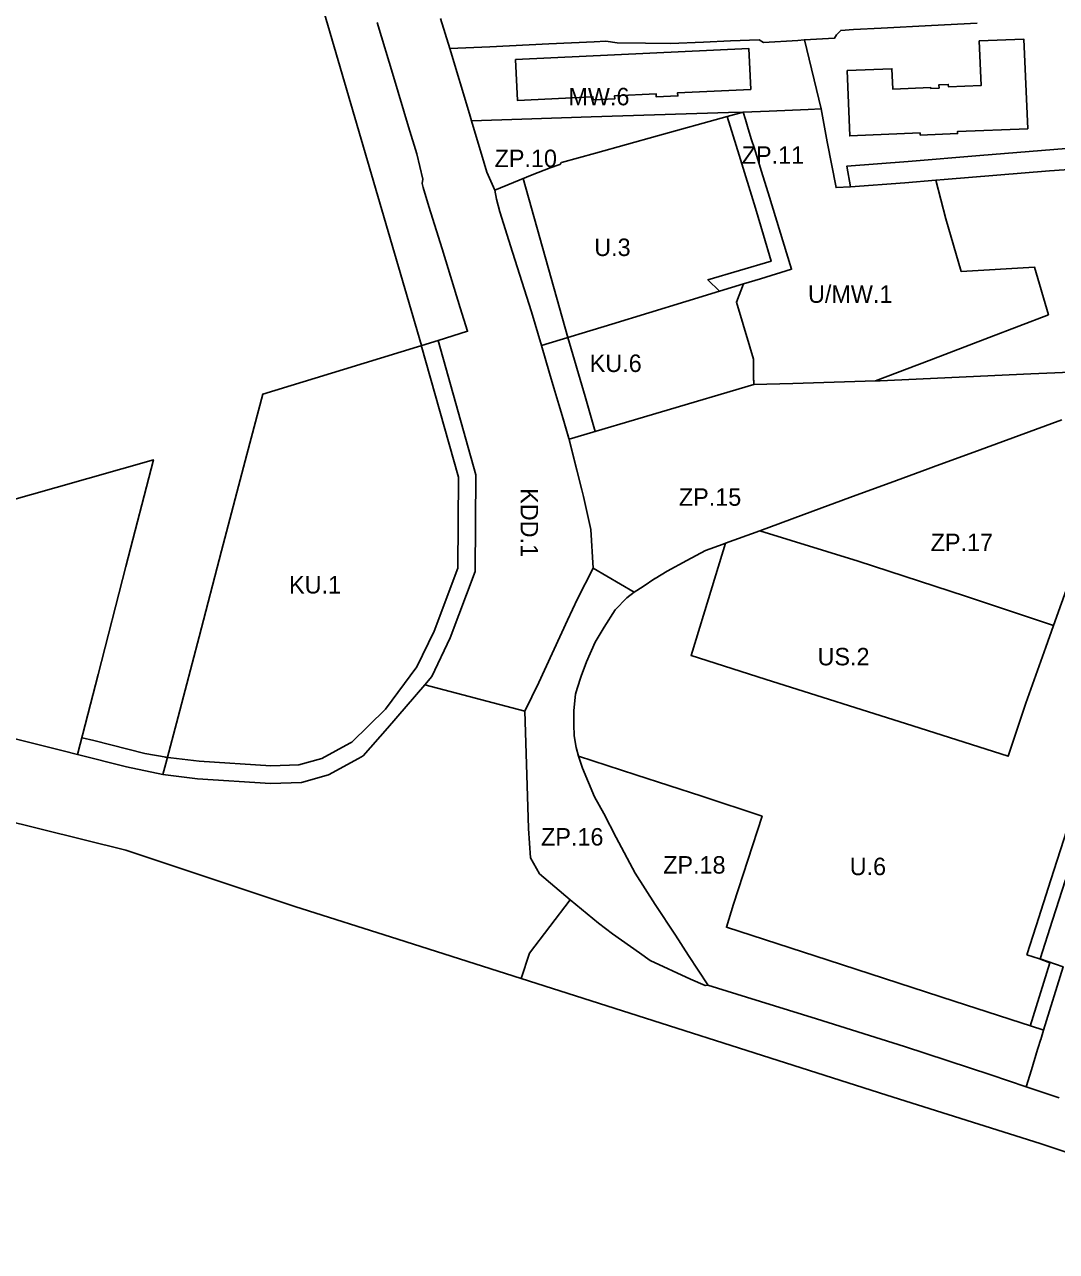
# Model space of a CAD drawing. Extents: x 7429178 to 7430831, y 5550228 to 5551611.
# Drawn here: x 7429876.2 to 7430171.5, y 5550864.2 to 5551215.2 of the extents above; entities that cross this region are included whole.
import ezdxf

# ---------------------------------------------------------------- set-up
doc = ezdxf.new("R2010")
doc.units = 0
for name, color, linetype in [('linie rozgraniczające', 7, 'Continuous'), ('nieprzekraczalne linie zabudowy', 7, 'Continuous'), ('obowiazujace linie zabudowy', 7, 'Continuous'), ('przeznaczenia terenów', 7, 'Continuous')]:
    doc.layers.add(name, color=color, linetype=linetype)

msp = doc.modelspace()

# ---------------------------------------------------------------- linework, layer by layer
at = {"layer": 'linie rozgraniczające'}
for points in [[(7429977.04, 5551215.75), (7429981.74, 5551200.32), (7429986.06, 5551185.97), (7429988.4, 5551178.21), (7429990.18, 5551170.95), (7429989.99, 5551169.68), (7429990.28, 5551168.62), (7429991.91, 5551163.18), (7429995.67, 5551151.03), (7430000.88, 5551134.16), (7430002.96, 5551127.44), (7430002.97, 5551127.43), (7429994.53, 5551124.85), (7429967.42, 5551116.51), (7429944.33, 5551109.41), (7429939.81, 5551092.17), (7429932.57, 5551064.59), (7429926.14, 5551040.05), (7429920.12, 5551017.1), (7429916.61, 5551003.74), (7429915.8, 5551000.65), (7429905.4, 5551002.83), (7429891.35, 5551006.35), (7429897.25, 5551029.27), (7429905.2, 5551060.11), (7429913.07, 5551090.69), (7429885.24, 5551082.78), (7429843.5, 5551070.94)], [(7429995.24, 5551216.96), (7429997.85, 5551208.32), (7430003.5, 5551189.65), (7430004.09, 5551187.66), (7430007.74, 5551175.52), (7430008.49, 5551173.01), (7430010.8, 5551167.85), (7430011.24, 5551165.28), (7430012.16, 5551161.61), (7430015.8, 5551150.1), (7430021.21, 5551133), (7430024.08, 5551123.34), (7430026.41, 5551115.47), (7430027.67, 5551111.24), (7430029.07, 5551106.52), (7430030.02, 5551103.31), (7430031.83, 5551097.19), (7430034.23, 5551087.73), (7430035.66, 5551082.05), (7430036.13, 5551080.22), (7430038.22, 5551070.72), (7430038.91, 5551059.68), (7430034.39, 5551050.87), (7430031.58, 5551044.81), (7430023.32, 5551026.92), (7430019.33, 5551018.76), (7429990.74, 5551026.27), (7429992.71, 5551028.7), (7429997.99, 5551039.71), (7430005.13, 5551058.76), (7430005.31, 5551086.38), (7429994.53, 5551124.85), (7430002.97, 5551127.43), (7430002.96, 5551127.44), (7430000.88, 5551134.16), (7429995.67, 5551151.03), (7429991.91, 5551163.18), (7429990.28, 5551168.62), (7429989.99, 5551169.68), (7429990.18, 5551170.95), (7429988.4, 5551178.21), (7429986.06, 5551185.97), (7429981.74, 5551200.32), (7429977.04, 5551215.75)], [(7430148.74, 5551215.55), (7430135.73, 5551214.89), (7430121.35, 5551214.15), (7430113.35, 5551213.78), (7430109.76, 5551213.53), (7430108.48, 5551212.25), (7430107.97, 5551211.33), (7430099.4, 5551210.8), (7430099.4, 5551210.8), (7430099.29, 5551210.79), (7430097.5, 5551210.68), (7430087.62, 5551210.09), (7430086.37, 5551210.87), (7430078.2, 5551210.53), (7430070.44, 5551210.12), (7430061.03, 5551209.8), (7430053.91, 5551209.87), (7430045.78, 5551209.94), (7430042.52, 5551210.44), (7430039.2, 5551210.29), (7430026.17, 5551209.67), (7430009.28, 5551208.86), (7429997.85, 5551208.32), (7429995.24, 5551216.96)], [(7430177.75, 5551180), (7430149.51, 5551177.75), (7430129.07, 5551175.98), (7430111.5, 5551174.69), (7430112.5, 5551168.78), (7430108.38, 5551168.53), (7430105.89, 5551181.65), (7430104.1, 5551191.07), (7430099.4, 5551210.8), (7430107.97, 5551211.33), (7430108.48, 5551212.25), (7430109.76, 5551213.53), (7430113.35, 5551213.78), (7430121.35, 5551214.15), (7430135.73, 5551214.89), (7430148.74, 5551215.55)], [(7430190.47, 5551174.81), (7430169.48, 5551173.32), (7430139.3, 5551170.86), (7430136.95, 5551170.65), (7430128.1, 5551169.87), (7430112.5, 5551168.78), (7430111.5, 5551174.69), (7430129.07, 5551175.98), (7430149.51, 5551177.75), (7430177.75, 5551180)], [(7430196.03, 5551116.65), (7430164.1, 5551115.22), (7430120.97, 5551113.28), (7430119.64, 5551113.24), (7430135.04, 5551119.12), (7430152.21, 5551125.68), (7430169.17, 5551132.16), (7430165.19, 5551145.77), (7430144.24, 5551144.57), (7430139.84, 5551159.6), (7430136.95, 5551170.65), (7430139.3, 5551170.86), (7430169.48, 5551173.32), (7430190.47, 5551174.81)], [(7430172.97, 5551102.13), (7430146.79, 5551092.52), (7430137.07, 5551088.95), (7430134.79, 5551088.11), (7430125.69, 5551084.77), (7430112.35, 5551079.87), (7430101.76, 5551075.98), (7430086.54, 5551070.39), (7430076.8, 5551066.81), (7430076.06, 5551066.54), (7430071.05, 5551064.7), (7430065.71, 5551061.82), (7430060.07, 5551058.78), (7430056.63, 5551056.73), (7430056.57, 5551056.69), (7430053.22, 5551054.44), (7430050.67, 5551052.81), (7430038.91, 5551059.68), (7430038.22, 5551070.72), (7430036.13, 5551080.22), (7430035.66, 5551082.05), (7430034.23, 5551087.73), (7430032, 5551096.54), (7430084.84, 5551112.21), (7430096.05, 5551112.54), (7430119.64, 5551113.24), (7430120.97, 5551113.28), (7430164.1, 5551115.22), (7430196.03, 5551116.65)], [(7430177.48, 5551062.44), (7430170.65, 5551043.22), (7430145.39, 5551051.68), (7430114.76, 5551061.67), (7430086.54, 5551070.39), (7430101.76, 5551075.98), (7430112.35, 5551079.87), (7430125.69, 5551084.77), (7430134.79, 5551088.11), (7430137.07, 5551088.95), (7430146.79, 5551092.52), (7430172.97, 5551102.13)], [(7429843.5, 5551070.94), (7429885.24, 5551082.78), (7429913.07, 5551090.69), (7429905.2, 5551060.11), (7429897.25, 5551029.27), (7429891.35, 5551006.35), (7429887.28, 5551007.37), (7429848.25, 5551017.16)], [(7430173.35, 5550945.62), (7430167.77, 5550927.5), (7430167.6, 5550927.55), (7430142.2, 5550935.8), (7430106.09, 5550947.51), (7430077.03, 5550956.94), (7430079.05, 5550963.55), (7430087.21, 5550988.7), (7430070.01, 5550994.41), (7430051.12, 5551000.56), (7430034.65, 5551005.92), (7430034, 5551008.41), (7430033.5, 5551011.69), (7430033.32, 5551014.96), (7430033.4, 5551018.91), (7430033.84, 5551023.64), (7430034.33, 5551025.21), (7430035.44, 5551028.77), (7430037.01, 5551032.9), (7430039.49, 5551038.49), (7430042.06, 5551042.8), (7430045.15, 5551047.71), (7430048.57, 5551051.21), (7430050.67, 5551052.81), (7430053.22, 5551054.44), (7430056.57, 5551056.69), (7430056.63, 5551056.73), (7430060.07, 5551058.78), (7430065.71, 5551061.82), (7430071.05, 5551064.7), (7430076.06, 5551066.54), (7430076.8, 5551066.81), (7430072.97, 5551054.35), (7430066.9, 5551034.64), (7430088.15, 5551027.91), (7430130.38, 5551014.54), (7430157.66, 5551005.87), (7430162.69, 5551021), (7430168.45, 5551037.07), (7430170.65, 5551043.22), (7430177.48, 5551062.44)], [(7429848.25, 5551017.16), (7429887.28, 5551007.37), (7429891.35, 5551006.35), (7429905.4, 5551002.83), (7429915.8, 5551000.65), (7429925.68, 5550999.44), (7429946.56, 5550998.11), (7429955.47, 5550998.39), (7429963.13, 5551000.52), (7429971.71, 5551005.22), (7429973.05, 5551005.95), (7429980.08, 5551013.9), (7429990.74, 5551026.27), (7430019.33, 5551018.76), (7430019.88, 5551000.53), (7430020.36, 5550985.18), (7430021, 5550976.76), (7430023.49, 5550972.25), (7430032.31, 5550964.82), (7430020.71, 5550949.51), (7430018.3, 5550942.25), (7429982.98, 5550953.52), (7429953.48, 5550962.92), (7429905.17, 5550978.96), (7429844.7, 5550993.98)], [(7430172.28, 5550908.16), (7430162.79, 5550911.32), (7430164.28, 5550916.14), (7430166.06, 5550921.92), (7430166.43, 5550923.14), (7430166.71, 5550924.04), (7430166.8, 5550924.34), (7430166.88, 5550924.61), (7430166.94, 5550924.78), (7430166.95, 5550924.84), (7430166.96, 5550924.86), (7430167.77, 5550927.5), (7430173.35, 5550945.62), (7430166.8, 5550947.9), (7430170.35, 5550958.95), (7430174.04, 5550970.46)], [(7430174.04, 5550970.46), (7430170.35, 5550958.95), (7430166.8, 5550947.9), (7430173.35, 5550945.62)], [(7430260.09, 5550864.18), (7430166.77, 5550895.04), (7430122.92, 5550908.88), (7430018.3, 5550942.25), (7430020.71, 5550949.51), (7430032.31, 5550964.82), (7430040.41, 5550958.06), (7430044.4, 5550955.04), (7430052.15, 5550949.63), (7430055.24, 5550947.42), (7430066.75, 5550942.05), (7430070.96, 5550940.23), (7430071.73, 5550940.39), (7430082.76, 5550936.96), (7430102.77, 5550930.72), (7430127.95, 5550922.78), (7430152.72, 5550914.67), (7430162.79, 5550911.32), (7430172.28, 5550908.16)]]:
    msp.add_lwpolyline(points, dxfattribs=at)
for points in [[(7430099.4, 5551210.8), (7430104.1, 5551191.07), (7430100.46, 5551190.91), (7430089.25, 5551190.45), (7430081.81, 5551190.17), (7430077.59, 5551190.02), (7430056.44, 5551189.34), (7430038.28, 5551188.76), (7430018.45, 5551188.12), (7430004.09, 5551187.66), (7430003.5, 5551189.65), (7429997.85, 5551208.32), (7430009.28, 5551208.86), (7430026.17, 5551209.67), (7430039.2, 5551210.29), (7430042.52, 5551210.44), (7430045.78, 5551209.94), (7430053.91, 5551209.87), (7430061.03, 5551209.8), (7430070.44, 5551210.12), (7430078.2, 5551210.53), (7430086.37, 5551210.87), (7430087.62, 5551210.09), (7430097.5, 5551210.68), (7430099.29, 5551210.79), (7430099.4, 5551210.8)], [(7430105.89, 5551181.65), (7430108.38, 5551168.53), (7430112.5, 5551168.78), (7430128.1, 5551169.87), (7430136.95, 5551170.65), (7430139.84, 5551159.6), (7430144.24, 5551144.57), (7430165.19, 5551145.77), (7430169.17, 5551132.16), (7430152.21, 5551125.68), (7430135.04, 5551119.12), (7430119.64, 5551113.24), (7430096.06, 5551112.54), (7430096.05, 5551112.54), (7430084.84, 5551112.21), (7430084.8, 5551114.31), (7430084.74, 5551119.48), (7430083.69, 5551123.02), (7430079.89, 5551135.8), (7430081.92, 5551141), (7430086.75, 5551142.47), (7430095.65, 5551145.17), (7430088.96, 5551167.01), (7430087.91, 5551170.41), (7430087.07, 5551173.14), (7430086.39, 5551175.33), (7430085.63, 5551177.79), (7430085.02, 5551179.75), (7430084.24, 5551182.26), (7430083.27, 5551185.38), (7430082.46, 5551188), (7430081.79, 5551190.15), (7430081.81, 5551190.17), (7430089.25, 5551190.45), (7430100.46, 5551190.91), (7430104.1, 5551191.07)], [(7430021.44, 5551172.23), (7430010.8, 5551167.85), (7430008.49, 5551173.01), (7430007.74, 5551175.52), (7430004.09, 5551187.66), (7430018.45, 5551188.12), (7430038.28, 5551188.76), (7430056.44, 5551189.34), (7430077.59, 5551190.02), (7430081.81, 5551190.17), (7430081.79, 5551190.15), (7430077.2, 5551188.87), (7430057.32, 5551183.34), (7430039.56, 5551178.41), (7430029.87, 5551175.71), (7430029.4, 5551175.12), (7430026.6, 5551174.17)], [(7430024.08, 5551123.34), (7430021.21, 5551133), (7430015.8, 5551150.1), (7430012.16, 5551161.61), (7430011.24, 5551165.28), (7430010.8, 5551167.85), (7430021.44, 5551172.23), (7430026.6, 5551174.17), (7430029.4, 5551175.12), (7430029.87, 5551175.71), (7430039.56, 5551178.41), (7430057.32, 5551183.34), (7430077.2, 5551188.87), (7430080.7, 5551177.78), (7430085.3, 5551162.69), (7430087.62, 5551154.94), (7430089.81, 5551147.48), (7430071.74, 5551142.2), (7430075.07, 5551138.92), (7430065.43, 5551135.98), (7430044.19, 5551129.49)], [(7430088.96, 5551167.01), (7430095.65, 5551145.17), (7430086.75, 5551142.47), (7430081.92, 5551141), (7430075.07, 5551138.92), (7430071.74, 5551142.2), (7430089.81, 5551147.48), (7430087.62, 5551154.94), (7430085.3, 5551162.69), (7430080.7, 5551177.78), (7430077.2, 5551188.87), (7430081.79, 5551190.15), (7430082.46, 5551188), (7430083.27, 5551185.38), (7430084.24, 5551182.26), (7430085.02, 5551179.75), (7430085.63, 5551177.79), (7430086.39, 5551175.33), (7430087.07, 5551173.14), (7430087.91, 5551170.41)], [(7430084.84, 5551112.21), (7430032, 5551096.54), (7430031.87, 5551097.03), (7430031.83, 5551097.19), (7430031.77, 5551097.41), (7430030.02, 5551103.31), (7430029.07, 5551106.52), (7430027.67, 5551111.24), (7430026.41, 5551115.47), (7430024.08, 5551123.34), (7430044.19, 5551129.49), (7430065.43, 5551135.98), (7430075.07, 5551138.92), (7430081.92, 5551141), (7430079.89, 5551135.8), (7430083.69, 5551123.02), (7430084.74, 5551119.48), (7430084.8, 5551114.31), (7430084.83, 5551112.65), (7430084.84, 5551112.22)], [(7429955.47, 5550998.39), (7429946.56, 5550998.11), (7429925.68, 5550999.44), (7429915.8, 5551000.65), (7429916.61, 5551003.74), (7429920.12, 5551017.1), (7429926.14, 5551040.05), (7429932.57, 5551064.59), (7429939.81, 5551092.17), (7429944.33, 5551109.41), (7429967.42, 5551116.51), (7429994.53, 5551124.85), (7430005.31, 5551086.38), (7430005.13, 5551058.76), (7429997.99, 5551039.71), (7429992.71, 5551028.7), (7429990.74, 5551026.27), (7429980.08, 5551013.9), (7429973.05, 5551005.95), (7429971.71, 5551005.22), (7429963.13, 5551000.52)], [(7430170.65, 5551043.22), (7430168.45, 5551037.07), (7430162.69, 5551021), (7430157.66, 5551005.87), (7430130.38, 5551014.54), (7430088.15, 5551027.91), (7430066.9, 5551034.64), (7430072.97, 5551054.35), (7430076.8, 5551066.81), (7430086.54, 5551070.39), (7430114.76, 5551061.67), (7430145.39, 5551051.68)], [(7430050.67, 5551052.81), (7430048.57, 5551051.21), (7430045.15, 5551047.71), (7430042.06, 5551042.8), (7430039.49, 5551038.49), (7430037.01, 5551032.9), (7430035.44, 5551028.77), (7430034.33, 5551025.21), (7430033.84, 5551023.64), (7430033.4, 5551018.91), (7430033.32, 5551014.96), (7430033.5, 5551011.69), (7430034, 5551008.41), (7430034.65, 5551005.92), (7430035.85, 5551002.42), (7430039.24, 5550994.28), (7430041.91, 5550989.44), (7430045.49, 5550982.63), (7430050.87, 5550972.38), (7430056.68, 5550963.48), (7430062.44, 5550954.65), (7430066.19, 5550948.9), (7430071.69, 5550940.47), (7430071.73, 5550940.39), (7430070.96, 5550940.23), (7430066.75, 5550942.05), (7430055.24, 5550947.42), (7430052.15, 5550949.63), (7430044.4, 5550955.04), (7430040.41, 5550958.06), (7430032.31, 5550964.82), (7430023.49, 5550972.25), (7430021, 5550976.76), (7430020.36, 5550985.18), (7430019.88, 5551000.53), (7430019.33, 5551018.76), (7430023.32, 5551026.92), (7430031.58, 5551044.81), (7430034.39, 5551050.87), (7430038.91, 5551059.68)], [(7430106.09, 5550947.51), (7430142.2, 5550935.8), (7430167.6, 5550927.55), (7430167.77, 5550927.5), (7430167.77, 5550927.5), (7430166.96, 5550924.86), (7430166.95, 5550924.84), (7430166.95, 5550924.84), (7430166.94, 5550924.78), (7430166.88, 5550924.61), (7430166.8, 5550924.34), (7430166.71, 5550924.04), (7430166.43, 5550923.14), (7430166.06, 5550921.92), (7430164.28, 5550916.14), (7430162.79, 5550911.32), (7430152.72, 5550914.67), (7430127.95, 5550922.78), (7430102.77, 5550930.72), (7430082.76, 5550936.96), (7430071.73, 5550940.39), (7430071.69, 5550940.47), (7430066.19, 5550948.9), (7430062.44, 5550954.65), (7430056.68, 5550963.48), (7430050.87, 5550972.38), (7430045.49, 5550982.63), (7430041.91, 5550989.44), (7430039.24, 5550994.28), (7430035.85, 5551002.42), (7430034.65, 5551005.92), (7430051.12, 5551000.56), (7430070.01, 5550994.41), (7430087.21, 5550988.7), (7430079.05, 5550963.55), (7430077.03, 5550956.94)]]:
    msp.add_lwpolyline(points, close=True, dxfattribs=at)
at = {"layer": 'nieprzekraczalne linie zabudowy'}
for points in [[(7429989.75, 5551123.38), (7429918.87, 5551365.77), (7429918.29, 5551367.92), (7429917.17, 5551372.03)], [(7430018.85, 5551171.17), (7430031.68, 5551125.67), (7430036.58, 5551108.79), (7430039.47, 5551098.76)], [(7429916.41, 5551005.61), (7429926.14, 5551004.42), (7429946.64, 5551003.11), (7429954.71, 5551003.36), (7429961.23, 5551005.18), (7429969.31, 5551009.6), (7429969.86, 5551009.91), (7429979.48, 5551019.32), (7429988.46, 5551031.4), (7429993.39, 5551041.67), (7430000.14, 5551059.68), (7430000.31, 5551085.71), (7429989.72, 5551123.5)], [(7430162.97, 5550949.06), (7430165.63, 5550957.33), (7430169.85, 5550970.48), (7430174.4, 5550984.68), (7430178.74, 5550998.18), (7430183.66, 5551013.4), (7430189.13, 5551030.33), (7430194.45, 5551046.81), (7430195.88, 5551051.23), (7430194.95, 5551058.17)], [(7429892.71, 5551011.17), (7429895.98, 5551010.35), (7429910.57, 5551006.69), (7429916.7, 5551005.57)], [(7430169.53, 5550946.8), (7430166.59, 5550947.86), (7430162.97, 5550949.06)], [(7430163.95, 5550928.67), (7430169.53, 5550946.8)]]:
    msp.add_lwpolyline(points, dxfattribs=at)
at = {"layer": 'obowiazujace linie zabudowy'}
for points in [[(7430163.23, 5551185.39), (7430162.09, 5551211.04), (7430149.35, 5551210.53), (7430149.87, 5551197.75), (7430140.54, 5551197.38), (7430140.52, 5551198.05), (7430137.83, 5551197.98), (7430137.87, 5551197.01), (7430135.5, 5551196.92), (7430135.49, 5551197.17), (7430124.62, 5551196.73), (7430124.39, 5551202.56), (7430111.58, 5551202.05), (7430112.32, 5551183.34), (7430132.45, 5551184.17), (7430132.48, 5551183.56), (7430143.15, 5551183.98), (7430143.12, 5551184.58), (7430163.23, 5551185.39)], [(7430016.64, 5551205.22), (7430017.22, 5551193.48), (7430038.82, 5551194.55), (7430038.87, 5551193.62), (7430045.07, 5551193.9), (7430045.02, 5551194.83), (7430056.88, 5551195.41), (7430056.93, 5551194.49), (7430063.14, 5551194.8), (7430063.07, 5551195.7), (7430083.99, 5551196.66), (7430083.42, 5551208.37), (7430016.64, 5551205.22)]]:
    msp.add_lwpolyline(points, dxfattribs=at)

# ---------------------------------------------------------------- texts
at = {"layer": 'przeznaczenia terenów'}
for s, p in [('MW.6', (7430031.81, 5551192.09)), ('ZP.11', (7430081.41, 5551175.36)), ('ZP.10', (7430010.69, 5551174.41)), ('U.3', (7430039.2, 5551148.97)), ('U/MW.1', (7430100.37, 5551135.58)), ('KU.6', (7430037.91, 5551115.79)), ('ZP.15', (7430063.43, 5551077.52)), ('ZP.17', (7430135.46, 5551064.55)), ('KU.1', (7429951.87, 5551052.42)), ('US.2', (7430103.1, 5551031.86)), ('ZP.16', (7430023.99, 5550980.31)), ('ZP.18', (7430058.93, 5550972.28)), ('U.6', (7430112.3, 5550971.84))]:
    msp.add_text(s, height=5, dxfattribs=at).set_placement(p)
msp.add_text('KDD.1', height=5, rotation=270, dxfattribs=at).set_placement((7430018.14, 5551082.54))

doc.saveas('drawing.dxf')
